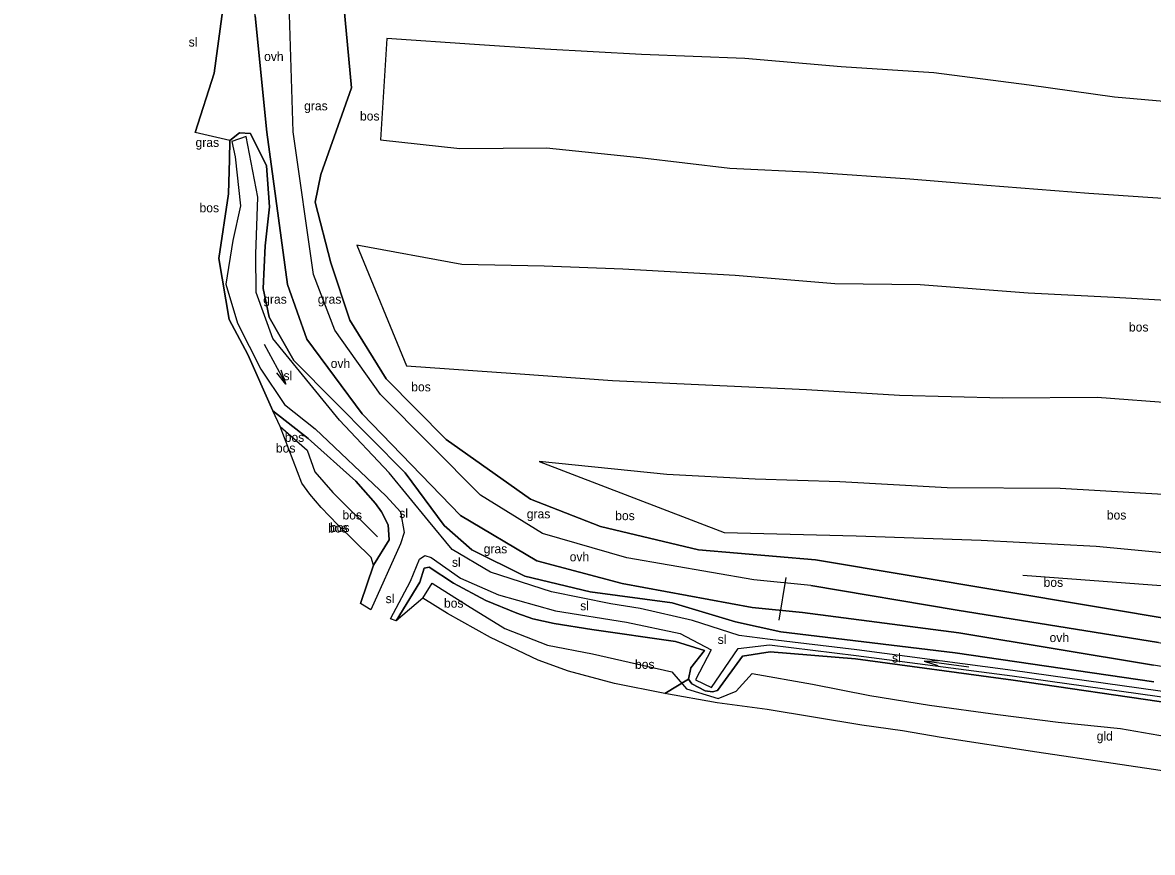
# Model space of a CAD drawing. Extents: x 154825 to 158680, y 370717 to 378075.
# Drawn here: x 155675.1 to 155799.6, y 376819.6 to 376911 of the extents above; entities that cross this region are included whole.
import ezdxf

# ---------------------------------------------------------------- set-up
doc = ezdxf.new("R2010")
doc.units = 0
for name, color, linetype in [('bos(vs)', 7, 'Continuous'), ('cultuurscheiding', 7, 'Continuous'), ('doorgang', 7, 'Continuous'), ('grasland_productiegrasl(vs)', 7, 'Continuous'), ('grazige vegetatie(vs)', 7, 'Continuous'), ('hoogteverschillijn', 7, 'Continuous'), ('insteek sloot', 7, 'Continuous'), ('maaiveldlijn algemeen - onverhard', 7, 'Continuous'), ('onverhard(vs)', 7, 'Continuous'), ('Sloot bodem', 7, 'Continuous'), ('sloot(vs)', 7, 'Continuous'), ('stroomrichting  watergangen', 7, 'Continuous'), ('vlak_Bos', 7, 'Continuous'), ('vlak_Grasland', 7, 'Continuous'), ('vlak_Grazige_vegetatie', 7, 'Continuous')]:
    doc.layers.add(name, color=color, linetype=linetype)

msp = doc.modelspace()

# ---------------------------------------------------------------- linework, layer by layer
at = {"layer": 'bos(vs)'}
msp.add_lwpolyline([(155707.98, 376936.31), (155709.06, 376926.66), (155710.19, 376916.09), (155711.3, 376903.83), (155707.93, 376894.26), (155707.32, 376891.22), (155709.05, 376884.55), (155711.14, 376878.22), (155715.14, 376871.74), (155721.77, 376865.05), (155731.05, 376858.48), (155738.77, 376855.49), (155749.59, 376852.93), (155762.49, 376851.8), (155803.11, 376845.02)], dxfattribs=at)
at = {"layer": 'cultuurscheiding'}
msp.add_lwpolyline([(155748.48, 376838.67), (155745.86, 376837.09)], dxfattribs=at)
at = {"layer": 'doorgang'}
msp.add_lwpolyline([(155759.21, 376849.88), (155758.43, 376845.16)], dxfattribs=at)
at = {"layer": 'hoogteverschillijn'}
for points in [[(155807.56, 376901.73), (155795.44, 376902.79), (155786.02, 376904.09), (155775.53, 376905.45), (155765.3, 376906.11), (155754.7, 376907.05), (155743.3, 376907.47), (155732.64, 376908.09), (155724.89, 376908.57), (155715.22, 376909.25), (155714.5, 376898.09), (155723.26, 376897.14), (155732.8, 376897.19), (155743.11, 376896.12), (155753.03, 376894.96), (155762.27, 376894.53), (155772.88, 376893.8), (155781.38, 376893.1), (155792.6, 376892.19), (155806.16, 376891.28)], [(155804.92, 376880.15), (155795.39, 376880.7), (155785.93, 376881.18), (155774, 376882.12), (155764.62, 376882.22), (155753.6, 376883.14), (155741.23, 376883.83), (155732.55, 376884.16), (155723.47, 376884.35), (155711.9, 376886.48), (155717.39, 376873.17), (155729.38, 376872.33), (155740.08, 376871.56), (155750.33, 376871.1), (155761.47, 376870.57), (155771.73, 376869.96), (155783.13, 376869.67), (155793.52, 376869.72), (155802.32, 376869.07)], [(155713.48, 376852.07), (155709.8, 376855.67), (155707.98, 376857.59), (155706.71, 376859.04), (155705.84, 376860.24), (155703.45, 376866.51), (155706.41, 376863.91), (155707.26, 376861.51), (155709.26, 376859.22), (155714.2, 376854.36)], [(155801.42, 376858.99), (155789.45, 376859.68), (155776.98, 376859.73), (155765.14, 376860.39), (155755.82, 376860.7), (155746.07, 376861.2), (155732.02, 376862.65), (155752.4, 376854.83), (155766.94, 376854.47), (155780.73, 376853.98), (155793.41, 376853.32), (155800.78, 376852.61)], [(155801.47, 376828.46), (155795.3, 376829.39), (155786.88, 376830.62), (155776.32, 376832.24), (155772.08, 376832.98), (155767.6, 376833.58), (155757.16, 376835.32), (155751.62, 376836.05), (155745.86, 376837.09), (155740.32, 376838.19), (155735.23, 376839.53), (155731.9, 376840.76), (155726.64, 376843.25), (155721.89, 376845.88), (155719.19, 376847.6), (155720.22, 376849.25), (155724.11, 376846.78), (155728.22, 376844.26), (155732.91, 376842.42), (155737.89, 376841.44), (155741.93, 376840.55), (155746.64, 376839.48), (155748.25, 376837.6), (155751.74, 376836.54), (155753.71, 376837.34), (155755.5, 376839.28), (155762.13, 376838.13), (155768.47, 376836.86), (155775.05, 376835.81), (155782.57, 376834.78), (155789.23, 376833.91), (155796.09, 376833.21), (155803.71, 376831.9)], [(155800.6, 376848.94), (155785.32, 376850.07)]]:
    msp.add_lwpolyline(points, dxfattribs=at)
at = {"layer": 'insteek sloot'}
for points in [[(155675.05, 377056.37), (155675.63, 377053.31), (155679.41, 377045.59), (155681.91, 377036.95), (155682.85, 377027.14), (155683.83, 377017.33), (155686.8, 376999.41), (155689.3, 376985.11), (155691.51, 376968.1), (155693.51, 376952.37), (155695.92, 376939.24), (155697.04, 376927.21), (155697.51, 376915.22), (155696.18, 376905.41), (155694.09, 376898.9)], [(155799.77, 376838.37), (155777.89, 376841.55), (155758.66, 376843.89), (155753.64, 376844.98), (155746.67, 376847.07), (155737.64, 376848.29), (155730.42, 376850.02), (155724.59, 376852.91), (155721.53, 376855.59), (155717.25, 376861.38), (155709.53, 376869.17), (155704.96, 376873.79), (155702.22, 376878.53), (155701.59, 376881.71), (155701.79, 376886.42), (155702.28, 376890.71), (155701.94, 376895.23), (155700.17, 376898.77), (155698.95, 376898.84), (155697.89, 376898.02), (155697.87, 376895.92), (155697.77, 376892.12), (155696.69, 376885.01), (155697.84, 376878.28), (155699.9, 376874.45), (155702.65, 376868.22), (155706.55, 376865.19), (155711.8, 376860.46), (155713.96, 376858.01), (155714.62, 376857.09), (155715.37, 376855.66), (155715.47, 376854.03), (155713.74, 376851.23), (155712.29, 376847)], [(155801.87, 376835.98), (155784.26, 376838.54), (155766.89, 376840.89), (155757.49, 376841.68), (155754.44, 376841.2), (155751.66, 376837.42), (155751.1, 376837.25), (155750.3, 376837.38), (155748.83, 376838.14), (155748.48, 376838.67), (155748.73, 376839.91), (155750.25, 376841.81), (155747.04, 376842.81), (155737.8, 376844.12), (155733.67, 376844.81), (155731.32, 376845.32), (155729.54, 376845.94), (155726.14, 376847.32), (155722.56, 376849.25), (155719.89, 376851.02), (155719.32, 376850.9), (155718.84, 376849.36), (155716.25, 376845.09)]]:
    msp.add_lwpolyline(points, dxfattribs=at)
at = {"layer": 'maaiveldlijn algemeen - onverhard'}
for points in [[(155761.03, 376845.99), (155755.5, 376846.57), (155741.14, 376849.22), (155731.75, 376851.69), (155723.34, 376856.68), (155712.5, 376867.89), (155706.39, 376876.14), (155704.25, 376882.16), (155701.97, 376898.91), (155700.7, 376911.76), (155698.71, 376927.73), (155696.14, 376945.4), (155693.09, 376968.37), (155688.9, 376994.4), (155685.69, 377015.23), (155683.13, 377037.65), (155677.23, 377056.7), (155675.8, 377073.11)], [(155761.97, 376849), (155755.68, 376849.59), (155741.67, 376852.04), (155732.37, 376854.7), (155725.54, 376858.93), (155714.5, 376870.01), (155709.49, 376877.13), (155707.13, 376883.25), (155704.89, 376898.96), (155704.46, 376913.05), (155702.37, 376928.28), (155698.99, 376946.56), (155695.61, 376968.87), (155692.55, 376995.44), (155689.46, 377015.57), (155687.2, 377038.78), (155681.05, 377057.6), (155675.8, 377073.11)], [(155761.97, 376849), (155778.08, 376846.25), (155800.28, 376842.69), (155818.67, 376839.48), (155840.9, 376835.86), (155860.13, 376833.5), (155881.4, 376830.99), (155903.31, 376829.04), (155916.93, 376827.42), (155923.18, 376826.59), (155927.44, 376827.44), (155929.98, 376827.65)], [(155927.76, 376819.58), (155925.74, 376822.59), (155921.05, 376823.98), (155916.67, 376825.04), (155903.18, 376826.77), (155881.48, 376828.86), (155859.8, 376831.07), (155840.39, 376833.74), (155818.23, 376837.16), (155799.73, 376840.22), (155778.26, 376843.76), (155761.03, 376845.99)]]:
    msp.add_lwpolyline(points, dxfattribs=at)
at = {"layer": 'Sloot bodem'}
for points in [[(155802.3, 376837.09), (155784.24, 376839.61), (155767.02, 376841.88), (155757.46, 376843.03), (155754.05, 376843.48), (155748.93, 376845.14), (155743.15, 376846.44), (155739.89, 376846.97), (155733.37, 376848.28), (155726.63, 376850.47), (155722.41, 376852.96), (155719.81, 376856.1), (155715.46, 376861.39), (155710.01, 376867.18), (155702.64, 376876.19), (155700.81, 376881.28), (155700.76, 376885.5), (155701, 376891.76), (155699.69, 376898.46), (155698.11, 376897.91), (155698.5, 376896.22), (155699.07, 376890.82), (155698.22, 376887.01), (155697.45, 376882.19), (155698.73, 376877.87), (155701.33, 376872.81), (155703.93, 376868.91), (155707.3, 376866.25), (155715.13, 376858.82), (155716.7, 376857.11), (155717.13, 376854.84), (155716.71, 376853.56), (155713.45, 376846.29)], [(155715.6, 376845.3), (155717.81, 376849.45), (155718.8, 376851.89), (155719.4, 376852.27), (155720.09, 376852.06), (155723.33, 376849.79), (155727.52, 376847.96), (155733.82, 376846.2), (155741.62, 376844.94), (155747.54, 376843.68), (155750.97, 376841.89), (155749.23, 376838.58), (155751.02, 376837.74), (155753.95, 376842.03), (155757.39, 376842.43), (155766.95, 376841.28), (155784.16, 376839.02), (155802.22, 376836.49)]]:
    msp.add_lwpolyline(points, dxfattribs=at)
at = {"layer": 'stroomrichting  watergangen'}
for p, q in [((155701.69, 376875.57), (155704.06, 376871.18)), ((155704.06, 376871.18), (155703.08, 376872.41)), ((155704.06, 376871.2), (155703.56, 376872.7)), ((155774.44, 376840.66), (155776.02, 376840.73)), ((155779.39, 376839.99), (155774.44, 376840.66)), ((155774.45, 376840.65), (155775.96, 376840.17))]:
    msp.add_line(p, q, dxfattribs=at)
at = {"layer": 'vlak_Bos'}
for points in [[(155804.24, 376845.73), (155803.11, 376845.02), (155762.49, 376851.8), (155749.59, 376852.93), (155738.77, 376855.49), (155731.05, 376858.48), (155721.77, 376865.05), (155715.14, 376871.74), (155711.14, 376878.22), (155709.05, 376884.55), (155707.32, 376891.22), (155707.93, 376894.26), (155711.3, 376903.83), (155710.19, 376916.09), (155709.06, 376926.66), (155707.98, 376936.31), (155710.74, 376938.93), (155711.93, 376937.32), (155749.4, 376933.71), (155779.55, 376931.02), (155798.58, 376929.34), (155817.7, 376927.17), (155811.74, 376900.95), (155807.72, 376874.51)], [(155715.47, 376854.03), (155713.74, 376851.23), (155713.48, 376852.07), (155709.8, 376855.67), (155707.98, 376857.59), (155706.71, 376859.04), (155705.84, 376860.24), (155703.45, 376866.51), (155702.65, 376868.22), (155706.55, 376865.19), (155711.8, 376860.46), (155713.96, 376858.01), (155714.62, 376857.09), (155715.37, 376855.66)], [(155722.56, 376849.25), (155726.14, 376847.32), (155729.54, 376845.94), (155731.32, 376845.32), (155733.67, 376844.81), (155737.8, 376844.12), (155747.04, 376842.81), (155750.25, 376841.81), (155748.73, 376839.91), (155748.48, 376838.67), (155745.86, 376837.09), (155740.32, 376838.19), (155735.23, 376839.53), (155731.9, 376840.76), (155726.64, 376843.25), (155721.89, 376845.88), (155719.19, 376847.6), (155716.25, 376845.09), (155718.84, 376849.36), (155719.32, 376850.9), (155719.89, 376851.02)]]:
    msp.add_lwpolyline(points, close=True, dxfattribs=at)
at = {"layer": 'vlak_Grasland'}
msp.add_lwpolyline([(155801.47, 376828.46), (155795.3, 376829.39), (155786.88, 376830.62), (155776.32, 376832.24), (155772.08, 376832.98), (155767.6, 376833.58), (155757.16, 376835.32), (155751.62, 376836.05), (155745.86, 376837.09), (155748.48, 376838.67), (155748.83, 376838.14), (155750.3, 376837.38), (155751.1, 376837.25), (155751.66, 376837.42), (155754.44, 376841.2), (155757.49, 376841.68), (155766.89, 376840.89), (155784.26, 376838.54), (155801.87, 376835.98)], dxfattribs=at)
at = {"layer": 'vlak_Grazige_vegetatie'}
for points in [[(155799.77, 376838.37), (155777.89, 376841.55), (155758.66, 376843.89), (155753.64, 376844.98), (155746.67, 376847.07), (155737.64, 376848.29), (155730.42, 376850.02), (155724.59, 376852.91), (155721.53, 376855.59), (155717.25, 376861.38), (155709.53, 376869.17), (155704.96, 376873.79), (155702.22, 376878.53), (155701.59, 376881.71), (155701.79, 376886.42), (155702.28, 376890.71), (155701.94, 376895.23), (155700.17, 376898.77), (155698.95, 376898.84), (155697.89, 376898.02), (155694.09, 376898.9), (155696.18, 376905.41), (155697.51, 376915.22)], [(155710.19, 376916.09), (155711.3, 376903.83), (155707.93, 376894.26), (155707.32, 376891.22), (155709.05, 376884.55), (155711.14, 376878.22), (155715.14, 376871.74), (155721.77, 376865.05), (155731.05, 376858.48), (155738.77, 376855.49), (155749.59, 376852.93), (155762.49, 376851.8), (155803.11, 376845.02)], [(155800.28, 376842.69), (155778.08, 376846.25), (155761.97, 376849), (155755.68, 376849.59), (155741.67, 376852.04), (155732.37, 376854.7), (155725.54, 376858.93), (155714.5, 376870.01), (155709.49, 376877.13), (155707.13, 376883.25), (155704.89, 376898.96), (155704.46, 376913.05)], [(155700.7, 376911.76), (155701.97, 376898.91), (155704.25, 376882.16), (155706.39, 376876.14), (155712.5, 376867.89), (155723.34, 376856.68), (155731.75, 376851.69), (155741.14, 376849.22), (155755.5, 376846.57), (155761.03, 376845.99), (155778.26, 376843.76), (155799.73, 376840.22)], [(155802.3, 376837.09), (155784.24, 376839.61), (155767.02, 376841.88), (155757.46, 376843.03), (155754.05, 376843.48), (155748.93, 376845.14), (155743.15, 376846.44), (155739.89, 376846.97), (155733.37, 376848.28), (155726.63, 376850.47), (155722.41, 376852.96), (155719.81, 376856.1), (155715.46, 376861.39), (155710.01, 376867.18), (155702.64, 376876.19), (155700.81, 376881.28), (155700.76, 376885.5), (155701, 376891.76), (155699.69, 376898.46), (155698.11, 376897.91), (155698.5, 376896.22), (155699.07, 376890.82), (155698.22, 376887.01), (155697.45, 376882.19), (155698.73, 376877.87), (155701.33, 376872.81), (155703.93, 376868.91), (155707.3, 376866.25), (155715.13, 376858.82), (155716.7, 376857.11), (155717.13, 376854.84), (155716.71, 376853.56), (155713.45, 376846.29), (155712.29, 376847), (155713.74, 376851.23), (155715.47, 376854.03), (155715.37, 376855.66), (155714.62, 376857.09), (155713.96, 376858.01), (155711.8, 376860.46), (155706.55, 376865.19), (155702.65, 376868.22), (155699.9, 376874.45), (155697.84, 376878.28), (155696.69, 376885.01), (155697.77, 376892.12), (155697.87, 376895.92), (155697.89, 376898.02), (155698.95, 376898.84), (155700.17, 376898.77), (155701.94, 376895.23), (155702.28, 376890.71), (155701.79, 376886.42), (155701.59, 376881.71), (155702.22, 376878.53), (155704.96, 376873.79), (155709.53, 376869.17), (155717.25, 376861.38), (155721.53, 376855.59), (155724.59, 376852.91), (155730.42, 376850.02), (155737.64, 376848.29), (155746.67, 376847.07), (155753.64, 376844.98), (155758.66, 376843.89), (155777.89, 376841.55), (155799.77, 376838.37)], [(155801.87, 376835.98), (155784.26, 376838.54), (155766.89, 376840.89), (155757.49, 376841.68), (155754.44, 376841.2), (155751.66, 376837.42), (155751.1, 376837.25), (155750.3, 376837.38), (155748.83, 376838.14), (155748.48, 376838.67), (155748.73, 376839.91), (155750.25, 376841.81), (155747.04, 376842.81), (155737.8, 376844.12), (155733.67, 376844.81), (155731.32, 376845.32), (155729.54, 376845.94), (155726.14, 376847.32), (155722.56, 376849.25), (155719.89, 376851.02), (155719.32, 376850.9), (155718.84, 376849.36), (155716.25, 376845.09), (155715.6, 376845.3), (155717.81, 376849.45), (155718.8, 376851.89), (155719.4, 376852.27), (155720.09, 376852.06), (155723.33, 376849.79), (155727.52, 376847.96), (155733.82, 376846.2), (155741.62, 376844.94), (155747.54, 376843.68), (155750.97, 376841.89), (155749.23, 376838.58), (155751.02, 376837.74), (155753.95, 376842.03), (155757.39, 376842.43), (155766.95, 376841.28), (155784.16, 376839.02), (155802.22, 376836.49)]]:
    msp.add_lwpolyline(points, dxfattribs=at)

# ---------------------------------------------------------------- texts
at = {"layer": 'bos(vs)'}
for p in [(155712.25, 376900.21), (155694.56, 376890.1), (155797.03, 376876.96), (155717.9, 376870.37), (155703.95, 376864.81), (155702.98, 376863.63), (155710.32, 376856.26), (155740.39, 376856.18), (155794.59, 376856.25), (155708.73, 376854.82), (155708.94, 376854.88), (155787.62, 376848.83), (155721.51, 376846.54), (155742.57, 376839.8)]:
    msp.add_text('bos', height=1, dxfattribs=at).set_placement(p)
at = {"layer": 'grasland_productiegrasl(vs)'}
msp.add_text('gld', height=1, dxfattribs=at).set_placement((155793.47, 376831.9))
at = {"layer": 'grazige vegetatie(vs)'}
for p in [(155706.09, 376901.33), (155694.12, 376897.3), (155701.58, 376880.03), (155707.6, 376880.03), (155730.64, 376856.38), (155725.89, 376852.53)]:
    msp.add_text('gras', height=1, dxfattribs=at).set_placement(p)
at = {"layer": 'onverhard(vs)'}
for p in [(155701.68, 376906.77), (155709.02, 376872.95), (155735.37, 376851.65), (155788.28, 376842.75)]:
    msp.add_text('ovh', height=1, dxfattribs=at).set_placement(p)
at = {"layer": 'sloot(vs)'}
for p in [(155693.36, 376908.36), (155703.82, 376871.6), (155716.58, 376856.44), (155722.39, 376851.04), (155715.08, 376847.04), (155736.53, 376846.25), (155751.69, 376842.55), (155770.91, 376840.5)]:
    msp.add_text('sl', height=1, dxfattribs=at).set_placement(p)

doc.saveas('drawing.dxf')
